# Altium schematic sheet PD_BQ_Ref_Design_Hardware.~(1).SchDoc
size 431 x 279 mm; Date: Not shown in title block; ApprovedBy: Not shown in title block; CheckedBy: Not shown in title block; Author: Not shown in title block; CompanyName: Not shown in title block; Engineer: Not shown in title block; Organization: Not shown in title block; Address1: Not shown in title block; Address2: Not shown in title block; Address3: Not shown in title block; Address4: Not shown in title block; DocumentNumber: 1; Revision: Use project parameter SCH_Rev; SheetNumber: 1; SheetTotal: 1; PageSetup: Record=PageOptions¦CenterHorizontal=True¦CenterVertical=True¦PrintScale=1.00¦XCorrection=1.00¦YCorrection=1.00¦PrintKind=0¦BorderSize=5000000¦LeftOffset=0¦BottomOffset=0¦Orientation=2¦PaperLength=1000¦PaperWidth=1000¦Scale=100¦PaperSource=15¦PrintQuality=600¦MediaType=1¦DitherType=10¦PaperKind=Letter¦PrintScaleMode=1
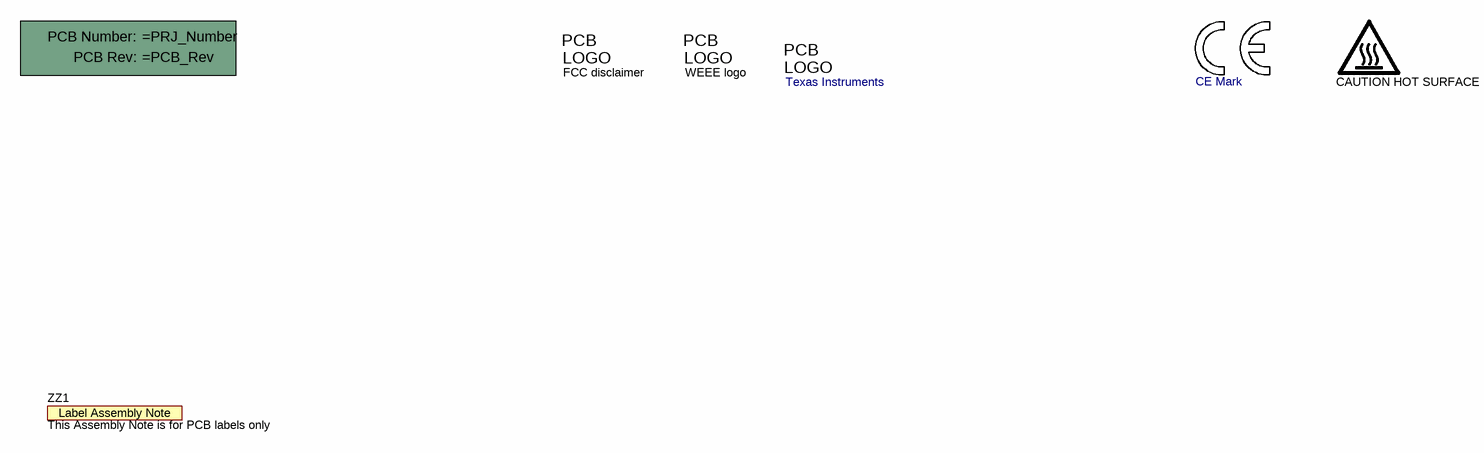
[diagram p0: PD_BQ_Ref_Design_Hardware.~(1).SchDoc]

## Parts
!PCB1  Printed Circuit Board  (value not drawn)  (mechanical)
Logo1  CE Mark  [CE_Mark_5mm]  (no BOM)
Logo2  Texas Instruments  [TI_Horizontal_Overlay_Small]  (no BOM)
Logo3  FCC disclaimer  [FCC_disclaimer]  (no BOM)
Logo4  WEEE logo  [WEEE_Minimum]  (no BOM)
LOGO5  CAUTION HOT SURFACE  [IEC_HotSurface_Small]  (no BOM)
ZZ1  This Assembly Note is for PCB labels only  [AssemblyNoteLabel]  (no BOM)

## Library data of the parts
!PCB1 = CMP-0003618-2: Manufacturer: Any
Logo1 = CMP-0074844-1: SymbolCreator: a0412235
Logo2 = CMP-0074838-1: Texas Instrument Corporate Signature; SymbolCreator: a0412235; Lib Reference: TI_Logo
Logo3 = CMP-0074847-1: FCC_disclaimer; Library Reference: Logo
Logo4 = CMP-0074769-1
LOGO5 = CMP-0074837-1: IEC 61010-1 Hot Surface Warning; SymbolCreator: a0412235
ZZ1 = CMP-0003616-3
